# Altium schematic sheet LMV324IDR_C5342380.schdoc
size 127 x 101 mm
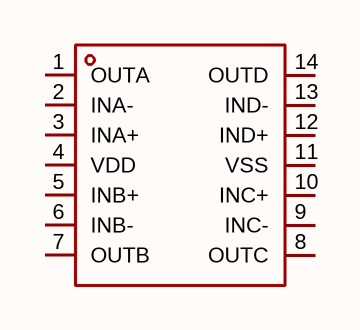
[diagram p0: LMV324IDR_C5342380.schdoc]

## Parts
U?  lmv324idr_c5342380  [SOP-14_L8.7-W3.9-P1.27-LS6.0-BL]  (value not drawn)

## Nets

Not connected (* = marked no-connect by the designer): U? 1(OUTA) 2(INA-) 3(INA+) 4(VDD) 5(INB+) 6(INB-) 7(OUTB) 8(OUTC) 9(INC-) 10(INC+) 11(VSS) 12(IND+) 13(IND-) 14(OUTD)

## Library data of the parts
U? = lmv324idr_c5342380: 放大器数:2;轨到轨:轨到轨输入,轨到轨输出;增益带宽积(GBW):1MHz;输入失调电压(Vos):5mV;压摆率(SR):600V/ms;输入偏置电流(Ib):10pA;; Manufacturer: TECH PUBLIC(台舟); AddInBom: yes; ModelId: 81979219354241bfb99806b876ac1c80; ModelTransform: 342.519,236.22,0,0,0,0,0,0,0; Number of Channels: 2; Maximum Power Supply Range (Vdd-Vss): 7V; Gain Bandwidth Product: 1MHz; Vos - Input Offset Voltage: 5mV; Input Offset Voltage Drift(Vos TC): 2uV/℃; Ib - Input Bias Current: 10pA; Input Voltage Noise Density: 20nV/√Hz@10kHz; Common Mode Rejection Ratio(CMRR): 80dB; Quiescent Current: 40uA; Output Current: 20mA; Single supply: 2.2V~5.5V; Dual Supply: 1.1V~2.75V；-2.75V~-1.1V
